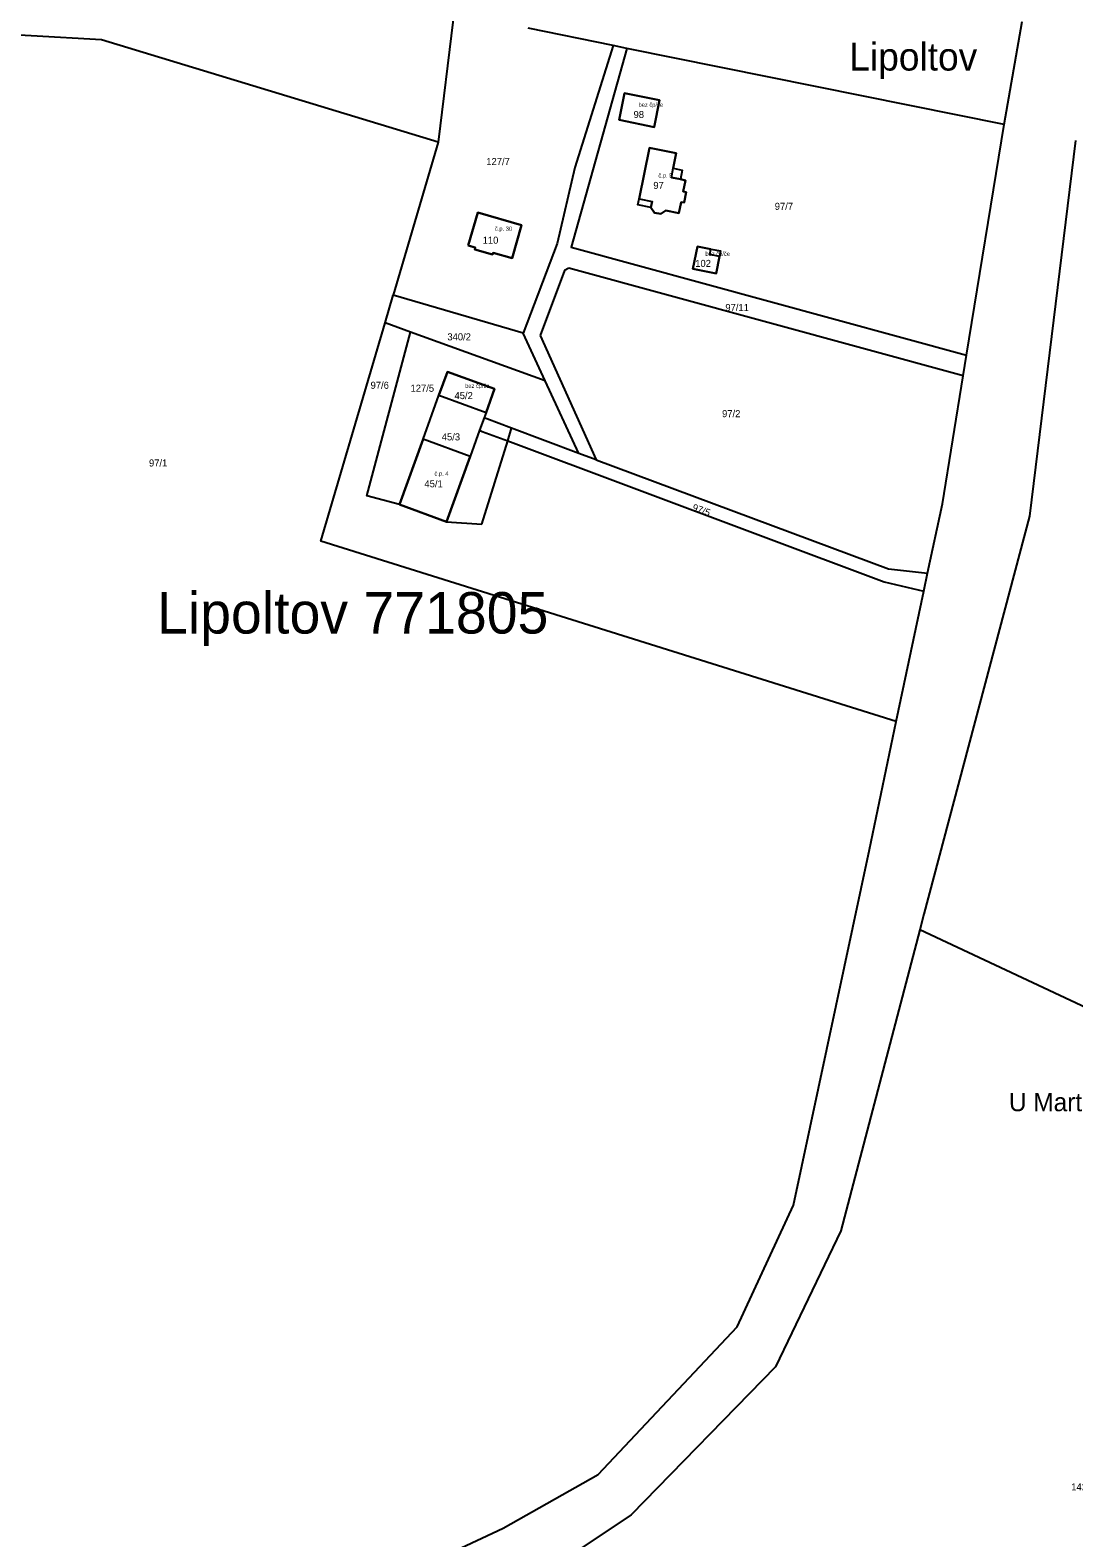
# Model space of a CAD drawing. Extents: x -880531 to -877616, y -1023932 to -1021350.
# Drawn here: x -879033.3 to -878781.4, y -1022969 to -1022605.2 of the extents above; entities that cross this region are included whole.
import ezdxf

# ---------------------------------------------------------------- set-up
doc = ezdxf.new("R2010")
doc.units = 0
for name, color, linetype in [('Definiční body', 7, 'Continuous'), ('Hranice parcel', 7, 'Continuous'), ('Parcelní čísla', 7, 'Continuous'), ('Polygon budovy', 7, 'Continuous'), ('Pop  PČ popisy', 7, 'Continuous'), ('Vnitřní kresba', 7, 'Continuous')]:
    doc.layers.add(name, color=color, linetype=linetype)

msp = doc.modelspace()

# ---------------------------------------------------------------- linework, layer by layer
at = {"layer": 'Hranice parcel'}
for p, q in [((-878798.29, -1022627.98), (-878793.89, -1022603.11)), ((-878892.61, -1022608.92), (-878913.11, -1022604.75)), ((-878889.33, -1022609.58), (-878892.61, -1022608.92)), ((-878798.29, -1022627.98), (-878889.33, -1022609.58)), ((-878807.35, -1022683.65), (-878798.29, -1022627.98)), ((-878934.82, -1022632.19), (-878945.69, -1022669.13)), ((-878808.16, -1022688.61), (-878903.34, -1022662.64)), ((-878947.65, -1022675.81), (-878945.69, -1022669.13)), ((-878914.32, -1022678.35), (-878945.69, -1022669.13)), ((-878941.5, -1022678.04), (-878947.65, -1022675.81)), ((-878909, -1022689.81), (-878941.5, -1022678.04)), ((-878909, -1022689.81), (-878914.32, -1022678.35)), ((-878910.23, -1022678.84), (-878896.75, -1022708.86)), ((-878808.16, -1022688.61), (-878807.35, -1022683.65)), ((-878900.87, -1022707.33), (-878909, -1022689.81)), ((-878938.5, -1022703.91), (-878934.65, -1022693.27)), ((-878934.65, -1022693.27), (-878923.29, -1022697.45)), ((-878923.29, -1022697.45), (-878923.76, -1022698.73)), ((-878924.85, -1022701.74), (-878927.14, -1022708.08)), ((-878923.76, -1022698.73), (-878924.85, -1022701.74)), ((-878924.85, -1022701.74), (-878924.22, -1022702.03)), ((-878923.09, -1022699.03), (-878923.76, -1022698.73)), ((-878944.21, -1022719.69), (-878938.5, -1022703.91)), ((-878927.14, -1022708.08), (-878938.5, -1022703.91)), ((-878896.75, -1022708.86), (-878900.87, -1022707.33)), ((-878817.67, -1022740.61), (-878816.73, -1022736.2)), ((-878824.34, -1022772.03), (-878817.67, -1022740.61)), ((-878666.02, -1022893.96), (-878818.61, -1022822.28))]:
    msp.add_line(p, q, dxfattribs=at)
for points in [[(-878930.92, -1022601.13), (-878931.26, -1022602.62), (-878934.82, -1022632.19)], [(-878934.82, -1022632.19), (-879016.09, -1022607.53), (-879050.15, -1022605.63), (-879088.97, -1022611.57), (-879141.92, -1022616.89), (-879193.77, -1022622.98), (-879220.93, -1022632.47), (-879233.1, -1022621.8), (-879243.76, -1022616.91), (-879278.47, -1022612.38), (-879323.11, -1022619.86), (-879374.6, -1022629.94), (-879401.23, -1022644.14)], [(-878892.61, -1022608.92), (-878901.85, -1022638.3), (-878906.1, -1022656.67), (-878914.32, -1022678.35)], [(-878889.33, -1022609.58), (-878902.72, -1022657.59), (-878807.35, -1022683.65)], [(-878889.87, -1022620.36), (-878881.4, -1022622.1), (-878882.72, -1022628.58), (-878891.2, -1022626.83), (-878889.87, -1022620.36)], [(-878781.06, -1022631.86), (-878792.13, -1022722.46), (-878817.64, -1022818.57), (-878818.61, -1022822.28)], [(-878874.97, -1022644.3), (-878875.48, -1022646.82), (-878876.22, -1022646.68), (-878876.76, -1022649.36), (-878879.88, -1022648.73), (-878881.14, -1022649.55), (-878882.65, -1022649.27), (-878883.51, -1022647.97), (-878886.64, -1022647.36), (-878886.35, -1022645.89), (-878883.84, -1022633.55), (-878877.43, -1022634.87), (-878878.14, -1022638.53), (-878875.95, -1022638.95), (-878876.38, -1022641.19), (-878875.18, -1022641.44), (-878875.72, -1022644.15), (-878874.97, -1022644.3)], [(-878927.59, -1022657.15), (-878925.29, -1022649.18), (-878914.7, -1022652.22), (-878917.03, -1022660.18), (-878921.59, -1022658.91), (-878921.74, -1022659.37), (-878926.03, -1022658.12), (-878925.9, -1022657.62), (-878927.59, -1022657.15)], [(-878869.04, -1022658.01), (-878866.71, -1022658.47), (-878866.97, -1022659.8), (-878867.76, -1022663.89), (-878873.37, -1022662.81), (-878872.24, -1022657.37), (-878869.04, -1022658.01)], [(-878903.34, -1022662.64), (-878904.37, -1022663.18), (-878910.23, -1022678.84)], [(-878824.34, -1022772.03), (-878963.16, -1022728.55), (-878947.65, -1022675.81)], [(-878944.21, -1022719.69), (-878952.03, -1022717.54), (-878941.5, -1022678.04)], [(-878934.65, -1022693.27), (-878932.61, -1022687.64), (-878921.23, -1022691.76), (-878923.29, -1022697.45)], [(-878816.73, -1022736.2), (-878813.18, -1022719.48), (-878808.16, -1022688.61)], [(-878900.87, -1022707.33), (-878917.12, -1022701.26), (-878923.09, -1022699.03)], [(-878924.22, -1022702.03), (-878918.07, -1022704.33), (-878827.19, -1022738.35), (-878817.67, -1022740.61)], [(-878927.14, -1022708.08), (-878932.84, -1022723.81), (-878944.21, -1022719.69)], [(-878896.75, -1022708.86), (-878826.18, -1022735.21), (-878816.73, -1022736.2)], [(-879246.38, -1023112.98), (-879192.09, -1023082.61), (-879135.36, -1023058.67), (-879046.78, -1023026.5), (-878919.16, -1022966.68), (-878896.25, -1022953.72), (-878862.71, -1022918.1), (-878849.11, -1022888.74), (-878830.77, -1022802.91), (-878824.34, -1022772.03)], [(-878818.61, -1022822.28), (-878837.64, -1022894.93), (-878853.43, -1022927.74), (-878888.27, -1022963.5), (-878906.95, -1022975.95)]]:
    msp.add_lwpolyline(points, dxfattribs=at)
at = {"layer": 'Polygon budovy'}
for points in [[(-878882.72, -1022628.58), (-878881.4, -1022622.1), (-878889.87, -1022620.36), (-878891.2, -1022626.83)], [(-878883.84, -1022633.55), (-878886.35, -1022645.89), (-878883.24, -1022646.52), (-878883.51, -1022647.97), (-878882.65, -1022649.27), (-878881.14, -1022649.55), (-878879.88, -1022648.73), (-878876.76, -1022649.36), (-878876.22, -1022646.68), (-878875.48, -1022646.82), (-878874.97, -1022644.3), (-878875.72, -1022644.15), (-878875.18, -1022641.44), (-878876.38, -1022641.19), (-878878.56, -1022640.73), (-878878.14, -1022638.53), (-878877.43, -1022634.87)], [(-878927.59, -1022657.15), (-878925.9, -1022657.62), (-878926.03, -1022658.12), (-878921.74, -1022659.37), (-878921.59, -1022658.91), (-878917.03, -1022660.18), (-878914.7, -1022652.22), (-878925.29, -1022649.18)], [(-878872.24, -1022657.37), (-878873.37, -1022662.81), (-878867.76, -1022663.89), (-878866.97, -1022659.8), (-878869.31, -1022659.33), (-878869.04, -1022658.01)], [(-878934.65, -1022693.27), (-878923.29, -1022697.45), (-878921.23, -1022691.76), (-878932.61, -1022687.64)], [(-878944.21, -1022719.69), (-878932.84, -1022723.81), (-878927.14, -1022708.08), (-878938.5, -1022703.91)]]:
    msp.add_lwpolyline(points, close=True, dxfattribs=at)
at = {"layer": 'Vnitřní kresba'}
for p, q in [((-878878.56, -1022640.73), (-878878.14, -1022638.53)), ((-878878.56, -1022640.73), (-878876.38, -1022641.19)), ((-878886.35, -1022645.89), (-878883.24, -1022646.52)), ((-878883.51, -1022647.97), (-878883.24, -1022646.52)), ((-878869.31, -1022659.33), (-878869.04, -1022658.01)), ((-878866.97, -1022659.8), (-878869.31, -1022659.33)), ((-878918.07, -1022704.33), (-878917.12, -1022701.26)), ((-878924.29, -1022724.41), (-878918.07, -1022704.33)), ((-878932.84, -1022723.81), (-878924.29, -1022724.41))]:
    msp.add_line(p, q, dxfattribs=at)

# ---------------------------------------------------------------- texts
at = {"layer": 'Definiční body'}
for s, p in [('bez čp/če', (-878886.49, -1022623.68)), ('č.p. 5', (-878881.71, -1022640.76)), ('č.p. 30', (-878921.16, -1022653.6)), ('bez čp/če', (-878870.35, -1022659.66)), ('bez čp/če', (-878928.34, -1022691.52)), ('č.p. 4', (-878935.73, -1022712.68))]:
    msp.add_text(s, height=1, dxfattribs=at).set_placement(p)
at = {"layer": 'Parcelní čísla'}
for s, p in [('98', (-878887.7, -1022626.4)), ('127/7', (-878923.236, -1022637.75)), ('97', (-878882.93, -1022643.51)), ('97/7', (-878853.63, -1022648.56)), ('110', (-878924.114, -1022656.73)), ('102', (-878872.816, -1022662.33)), ('97/11', (-878865.553, -1022672.98)), ('340/2', (-878932.63, -1022680.05)), ('97/6', (-878951.16, -1022691.74)), ('127/5', (-878941.52, -1022692.46)), ('45/2', (-878930.91, -1022694.23)), ('97/2', (-878866.34, -1022698.59)), ('45/3', (-878933.98, -1022704.2)), ('97/1', (-879004.63, -1022710.49)), ('45/1', (-878938.16, -1022715.51)), ('142/1', (-878782.08, -1022957.61))]:
    msp.add_text(s, height=1.7, dxfattribs=at).set_placement(p)
msp.add_text('97/5', height=1.7, rotation=340, dxfattribs=at).set_placement((-878873.69, -1022721.048))
at = {"layer": 'Pop  PČ popisy'}
for s, height, p in [('Lipoltov', 6.7, (-878835.64, -1022614.94)), ('Lipoltov 771805', 10, (-879002.691, -1022750.807)), ('U Martina', 4.4, (-878797.11, -1022866.09))]:
    msp.add_text(s, height=height, dxfattribs=at).set_placement(p)

doc.saveas('drawing.dxf')
